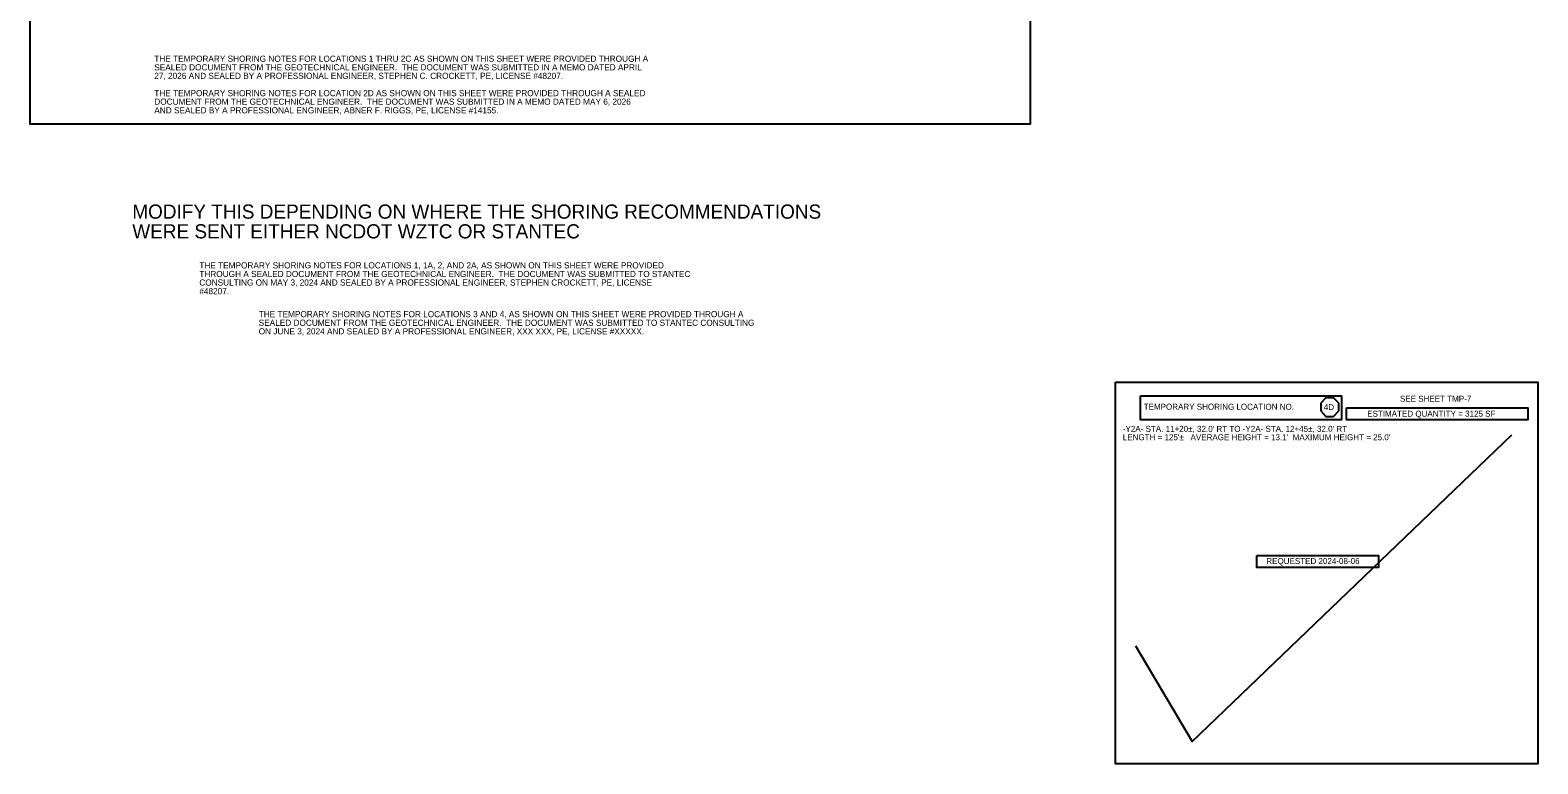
# Model space of a CAD drawing. Extents: x 2487012 to 2497594, y 369516 to 371986.
# Drawn here: x 2489017 to 2490728, y 369516 to 370349 of the extents above; entities that cross this region are included whole.
import ezdxf

# ---------------------------------------------------------------- set-up
doc = ezdxf.new("R2010")
doc.units = 0
for name, color, linetype in [('Scratch_Level_2', 7, 'Continuous'), ('Scratch_Level_6', 7, 'Continuous'), ('TC LABEL TEMP SHORING', 7, 'Continuous'), ('TC SHEET BORDER LINE THIN', 7, 'Continuous'), ('TC SHEET LAYOUT SHAPE', 7, 'Continuous'), ('TC SHEET TEXT', 7, 'Continuous')]:
    doc.layers.add(name, color=color, linetype=linetype)

msp = doc.modelspace()

# ---------------------------------------------------------------- linework, layer by layer
at = {"layer": 'Scratch_Level_2'}
msp.add_lwpolyline([(2490271.3, 369649.6), (2490335.6, 369541), (2490698.5, 369889.5)], dxfattribs=at)
at = {"layer": 'TC LABEL TEMP SHORING'}
for p, q in [((2490487.5, 369931.3), (2490481.5, 369925.2)), ((2490481.5, 369925.2), (2490481.5, 369916.4)), ((2490481.5, 369916.4), (2490487.5, 369910.3)), ((2490496.2, 369931.3), (2490487.5, 369931.3)), ((2490502.2, 369925.2), (2490496.2, 369931.3)), ((2490496.2, 369910.3), (2490502.2, 369916.4)), ((2490502.2, 369916.4), (2490502.2, 369925.2)), ((2490487.5, 369910.3), (2490496.2, 369910.3))]:
    msp.add_line(p, q, dxfattribs=at)
at = {"layer": 'TC SHEET BORDER LINE THIN'}
for points in [[(2490248.6, 369949.3), (2490728, 369949.3), (2490728, 369515.7), (2490248.6, 369515.7)], [(2490277.1, 369933.7), (2490505.1, 369933.7), (2490505.1, 369906.4), (2490277.1, 369906.4)], [(2490510.9, 369920.1), (2490716.7, 369920.1), (2490716.7, 369906.4), (2490510.9, 369906.4)], [(2490409, 369752.4), (2490547.1, 369752.4), (2490547.1, 369738.8), (2490409, 369738.8)]]:
    msp.add_lwpolyline(points, close=True, dxfattribs=at)
at = {"layer": 'TC SHEET LAYOUT SHAPE'}
msp.add_lwpolyline([(2489016.6, 370690.8), (2489016.6, 371000.2), (2489016.6, 371272.3), (2489026.6, 371282.3), (2489469.6, 371282.3), (2489940.6, 371282.3), (2490261.6, 371282.3), (2490261.6, 371202.3), (2490346.6, 371202.3), (2490346.6, 371250.3), (2490506.6, 371250.3), (2490506.6, 370915.3), (2490506.6, 370636.1), (2490506.6, 370384.8), (2490151.6, 370384.8), (2490151.6, 370242.3), (2489778.4, 370242.3), (2489608.9, 370242.3), (2489256.1, 370242.3), (2489016.6, 370242.3)], close=True, dxfattribs=at)

# ---------------------------------------------------------------- texts
at = {"layer": 'Scratch_Level_6'}
for s, p in [('MODIFY THIS DEPENDING ON WHERE THE SHORING RECOMMENDATIONS ', (2489132.5, 370134.8)), ('WERE SENT EITHER NCDOT WZTC OR STANTEC', (2489132.5, 370112.4))]:
    msp.add_text(s, height=16.094, dxfattribs=at).set_placement(p)
at = {"layer": 'TC LABEL TEMP SHORING'}
msp.add_text('4D', height=6.81, dxfattribs=at).set_placement((2490485.1, 369917.4))
at = {"layer": 'TC SHEET BORDER LINE THIN'}
msp.add_text('REQUESTED 2024-08-06', height=6.814, dxfattribs=at).set_placement((2490419.8, 369742.6))
at = {"layer": 'TC SHEET TEXT'}
for s, height, p in [('THE TEMPORARY SHORING NOTES FOR LOCATIONS 1 THRU 2C AS SHOWN ON THIS SHEET WERE PROVIDED THROUGH A ', 7, (2489157.5, 370313)), ('SEALED DOCUMENT FROM THE GEOTECHNICAL ENGINEER.  THE DOCUMENT WAS SUBMITTED IN A MEMO DATED APRIL ', 7, (2489157.5, 370303.2)), ('27, 2026 AND SEALED BY A PROFESSIONAL ENGINEER, STEPHEN C. CROCKETT, PE, LICENSE #48207.', 7, (2489157.5, 370293.5)), ('THE TEMPORARY SHORING NOTES FOR LOCATION 2D AS SHOWN ON THIS SHEET WERE PROVIDED THROUGH A SEALED ', 7, (2489157.5, 370273.9)), ('AND SEALED BY A PROFESSIONAL ENGINEER, ABNER F. RIGGS, PE, LICENSE #14155.', 7, (2489157.5, 370254.4)), ('DOCUMENT FROM THE GEOTECHNICAL ENGINEER.  THE DOCUMENT WAS SUBMITTED IN A MEMO DATED MAY 6, 2026 ', 7, (2489157.5, 370264.2)), ('THE TEMPORARY SHORING NOTES FOR LOCATIONS 1, 1A, 2, AND 2A, AS SHOWN ON THIS SHEET WERE PROVIDED ', 7, (2489208.6, 370078.3)), ('THROUGH A SEALED DOCUMENT FROM THE GEOTECHNICAL ENGINEER.  THE DOCUMENT WAS SUBMITTED TO STANTEC ', 7, (2489208.6, 370068.5)), ('#48207.', 7, (2489208.6, 370049)), ('CONSULTING ON MAY 3, 2024 AND SEALED BY A PROFESSIONAL ENGINEER, STEPHEN CROCKETT, PE, LICENSE ', 7, (2489208.6, 370058.8)), ('THE TEMPORARY SHORING NOTES FOR LOCATIONS 3 AND 4, AS SHOWN ON THIS SHEET WERE PROVIDED THROUGH A ', 7, (2489276, 370022.9)), ('SEALED DOCUMENT FROM THE GEOTECHNICAL ENGINEER.  THE DOCUMENT WAS SUBMITTED TO STANTEC CONSULTING ', 7, (2489276, 370013.1)), ('ON JUNE 3, 2024 AND SEALED BY A PROFESSIONAL ENGINEER, XXX XXX, PE, LICENSE #XXXXX.', 7, (2489276, 370003.4)), ('SEE SHEET TMP-7', 6.814, (2490571.5, 369926.9)), ('TEMPORARY SHORING LOCATION NO.', 6.814, (2490280.6, 369917.8)), ('ESTIMATED QUANTITY = 3125 SF', 6.814, (2490534.3, 369909.9)), ("-Y2A- STA. 11+20±, 32.0' RT TO -Y2A- STA. 12+45±, 32.0' RT", 6.814, (2490256.9, 369892.7)), ("LENGTH = 125'±   AVERAGE HEIGHT = 13.1'  MAXIMUM HEIGHT = 25.0'", 6.814, (2490256.9, 369883.2))]:
    msp.add_text(s, height=height, dxfattribs=at).set_placement(p)

doc.saveas('drawing.dxf')
